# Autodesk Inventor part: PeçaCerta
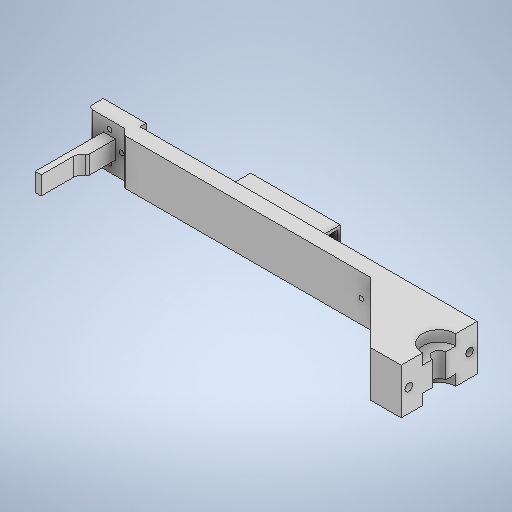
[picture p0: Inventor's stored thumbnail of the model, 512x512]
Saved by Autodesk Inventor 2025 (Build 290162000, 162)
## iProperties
Created: 2025-03
Part Number: PeçaCerta
Material: Genérico
Document SubType Name: Modeling
Designer: Ian
Density: 1 g/cm^3
Appearance: Padrão
Mass: 116.041 g
Surface Area: 272.444 cm^2
Volume: 116.041 cm^3
Author: Ian
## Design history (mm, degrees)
sketch "Esboço1"
  geometry: L1 (0, 9.81)-(0, -11.11) reference; L2 (-6.302, 0)-(16.322, 0) reference; L3 (-14.1, 15)-(235.9, 15); L4 (235.9, 15)-(235.9, -15); L5 (235.9, -15)-(-14.1, -15); L6 (-14.1, -15)-(-14.1, 15); C1 r 1.6 at (-0.001, -9.5); C2 r 1.6 at (8, 0); C3 r 1.6 at (-8, 0); C4 r 3 at (0, 0); C5 r 1.6 at (0, 9.5); 2 further points
  constraints: 12 end point, 5 centre point, 3 horizontal, 2 equal radius, 2 point on line, 2 vertical, 1 coincident, 1 midpoint, 1 parallel, 1 perpendicular
  dimensions: "d13" = 18.99994 distance of C5.centre C1.centre; "d37" = 9.21961 dimension on C1 C3; "d38" = 9.21974 dimension on C5 C3; "d39" = 9.21977 dimension on C2 C5; "d42" = 6.00008 diameter of C4; "d43" = 16 distance of C2.centre C3.centre; "d45" = 9.22072 dimension on C1 C2; "d46" = 4.5 distance edge to line of C3 L6; "d47" = 250 distance of L3.start L3.end; "d48" = 30 distance of L5.end L3.start; "d49" = 0 vertical distance of C4.centre point (-14.1, 0)
extrude "Extrusão7" new body sketch "Esboço1" distance "d50" = 10; taper "d51" = 0 deg
sketch "Esboço10"
  geometry: L1 (-135.9, 15)-(-76.9, 15) reference; L2 (-76.9, 15)-(-76.9, -15); L3 (-76.9, -15)-(-135.9, -15); L4 (-135.9, -15)-(-135.9, 15); L5 (-135.9, 15)-(-76.9, -15); L6 (-76.9, 15)-(-135.9, -15); L7 (-135.9, 13.5)-(-76.9, 13.5); L8 (-76.9, -13.5)-(-135.9, -13.5); L9 (-235.9, -15)-(-235.9, 15) reference; C1 r 1.6 at (-8, 0) reference; 2 further points
  constraints: 16 end point, 4 point on line, 3 horizontal, 3 parallel, 2 midpoint, 1 perpendicular
  dimensions: "d135" = 59 distance of L2.end L3.end; "d136" = 30 distance of L1.end L2.end; "d180" = 1.5 distance between parallel lines of L3 L8; "d181" = 1.5 distance between parallel lines of L1 L7; "d182" = 100 distance between parallel lines of L9 L4
extrude "Extrusão8" join sketch "Esboço10" distance "d58" = 10; taper "d59" = 0 deg
sketch "Esboço13"
  geometry: L1 (14.1, -15)-(-235.9, -15) reference; L2 (14.1, 15)-(14.1, -15) reference; L3 (-14.1, 15)-(14.1, 15); L4 (14.1, 15)-(14.1, -15); L5 (14.1, -15)-(-14.1, -15); L6 (-14.1, -15)-(-14.1, 15); L7 (-14.1, 15)-(14.1, -15); L8 (14.1, 15)-(-14.1, -15); C1 r 1.6 at (8, 0) reference; C2 r 3 at (0, 0) reference; C3 r 1.6 at (0.001, -9.5) reference; C4 r 1.6 at (-8, 0) reference; C5 r 1.6 at (0, 9.5) reference; C6 r 3 at (0, 0); C7 r 1.6 at (-8, 0); C8 r 1.6 at (0.001, -9.5); C9 r 1.6 at (8, 0); C10 r 1.6 at (0, 9.5); 4 further points
  constraints: 12 end point, 5 centre point, 5 coincident, 5 concentric, 2 midpoint, 2 parallel, 1 horizontal, 1 perpendicular, 1 point on line
extrude "Extrusão11" join sketch "Esboço13" distance "d70" = 4; taper "d71" = 0 deg
sketch "Esboço14"
  geometry: L1 (235.9, 15)-(-14.1, 15) reference; L2 (14.1, -15)-(-14.1, -15); L3 (-14.1, -15)-(-14.1, 15); L4 (-14.1, 15)-(14.1, 15); L5 (14.1, 15)-(14.1, -15); L6 (14.1, -15)-(-14.1, 15); L7 (-14.1, -15)-(14.1, 15); 2 further points
  constraints: 12 end point, 2 midpoint, 2 parallel, 1 horizontal, 1 perpendicular
extrude "Extrusão12" cut sketch "Esboço14" distance "d72" = 4; taper "d73" = 0 deg
sketch "Esboço15"
  geometry: L1 (0, 0)-(-221.801, 0) reference; L2 (-221.801, 0)-(-225.801, 4); L3 (-221.801, 0)-(-216.144, 0); L4 (-225.801, 4)-(-221.801, 4); L5 (-221.801, 4)-(-221.801, 0); 1 further point
  constraints: 8 end point, 2 horizontal, 1 equal length, 1 perpendicular
  dimensions: "d74" = 135 deg angle of L3 L2
extrude "Extrusão13" join sketch "Esboço15" stored distance "d75" = 4; taper "d76" = 0 deg
fillet "Arredondamento4" dims "d78" = 1
fillet "Arredondamento5" dims "d79" = 3
sketch "Esboço18"
  geometry: L1 (14.1, -15)-(235.9, -15) reference; L2 (235.9, 15)-(14.1, 15) reference; L3 (235.9, -15)-(175.9, -15); L4 (175.9, -15)-(175.9, 15); L5 (175.9, 15)-(235.9, 15); L6 (235.9, 15)-(235.9, -15); 3 further points
  constraints: 8 end point, 2 parallel, 1 horizontal, 1 perpendicular, 1 point on line
  dimensions: "d81" = 60 distance of L4.end L5.end
extrude "Extrusão14" join sketch "Esboço18" distance "d82" = 40; taper "d83" = 0 deg
sketch "Esboço19"
  geometry: L1 (0.414, 10)-(161.801, 10) reference; L2 (161.801, 10)-(201.801, 50); L3 (221.801, 50)-(161.801, 50) reference; L4 (201.801, 50)-(161.801, 50); L5 (161.801, 10)-(161.801, 50); 2 further points
  constraints: 6 end point, 1 collinear, 1 perpendicular, 1 point on line
  dimensions: "d84" = 45 deg angle of L3 L2
extrude "Extrusão15" cut sketch "Esboço19" extent not by distance; stored distance "d85" = 0; taper "d86" = 0 deg
sketch "Esboço20"
  geometry: L1 (161.801, 10)-(221.801, 10); L2 (221.801, 0)-(221.801, 50) reference; L3 (221.801, 50)-(201.801, 50) reference; L4 (201.801, 50)-(191.801, 10); C1 r 10.975 at (221.801, 25); 3 further points
  constraints: 4 end point, 2 midpoint, 1 centre point, 1 horizontal, 1 point on line
  dimensions: "d87" = 21.95 diameter of C1
extrude "Extrusão16" cut sketch "Esboço20" distance "d88" = 7; taper "d89" = 0 deg
sketch "Esboço21"
  geometry: L1 (221.801, 35.975)-(221.801, 14.025) reference; C1 r 4.25 at (221.801, 25); A1 r 10.975 centre (221.801, 25) between (221.801, 35.975) and (221.801, 14.025) reference; 3 further points
  constraints: 1 centre point, 1 coincident
  dimensions: "d90" = 8.5 diameter of C1
extrude "Extrusão17" cut sketch "Esboço21" extent not by distance; stored distance "d91" = 0; taper "d92" = 0 deg
sketch "Esboço22"
  geometry: C1 r 10.975 at (221.801, -25); A1 r 4.25 centre (221.801, -25) between (221.801, -20.75) and (221.801, -29.25) reference; 1 further point
  constraints: 1 centre point, 1 coincident
  dimensions: "d93" = 21.95 diameter of C1; "d173" = 4.25 radius of A1 (derived)
extrude "Extrusão18" cut sketch "Esboço22" distance "d94" = 7; taper "d95" = 0 deg
sketch "Esboço23"
  geometry: L1 (-14.025, 30)-(-14.025, 23) reference; L2 (-14.025, 7)-(-14.025, 0) reference; L3 (-10, 0)-(-10, 30) reference; L4 (-10, 30)-(0, 30); L5 (0, 15)-(-50, 15); L6 (-50, 30)-(-50, 0) reference; L7 (-20.75, 23)-(-20.75, 7) reference; L8 (-29.25, 7)-(-29.25, 23) reference; C1 r 2.5 at (-5, 15); C2 r 2.5 at (-45, 15)
  constraints: 4 end point, 2 centre point, 1 horizontal, 1 midpoint, 1 point on line
  dimensions: "d96" = 5 diameter of C1; "d174" = 15.75 distance from line of L7 C1.centre; "d175" = 5 diameter of C2; "d177" = 15.75 distance from line of L8 C2.centre
extrude "Extrusão19" cut sketch "Esboço23" distance "d97" = 50; taper "d98" = 0 deg
sketch "Esboço24"
  geometry: L1 (-235.9, -2.5)-(-235.9, 2.5) reference; L2 (-175.9, -15)-(-175.9, 15) reference; L3 (-183.4, -12.5)-(-208.4, -12.5); L4 (-208.4, -12.5)-(-208.4, 12.5); L5 (-208.4, 12.5)-(-183.4, 12.5); L6 (-183.4, 12.5)-(-183.4, -12.5); L7 (-183.4, -12.5)-(-208.4, 12.5); L8 (-208.4, -12.5)-(-183.4, 12.5); 1 further point
  constraints: 12 end point, 2 parallel, 1 horizontal, 1 perpendicular
  dimensions: "d101" = 25 distance of L4.end L5.end; "d102" = 25 distance of L3.end L4.end
extrude "Extrusão20" cut sketch "Esboço24" extent not by distance; stored distance "d103" = 0; taper "d104" = 0 deg
sketch "Esboço33"
  geometry: L1 (-235.9, -15)-(-235.9, 15) reference; C1 r 1.5 at (-169.604, 0); 2 further points
  constraints: 1 centre point, 1 coincident
  dimensions: "d121" = 3 diameter of C1; "d122" = 66.2965 distance from line of C1.centre L1
extrude "Extrusão25" cut sketch "Esboço33" distance "d132" = 10; taper "d133" = 0 deg
sketch "Esboço35"
  geometry: L1 (10, 30)-(10, 0) reference; L2 (8, 28)-(0, 28); L3 (0, 28)-(0, 2); L4 (0, 2)-(8, 2); L5 (8, 2)-(8, 28); L6 (0, 30)-(10, 30) reference; L7 (0, 30)-(0, 0); L8 (-0.005, 28.797)-(-0.005, 0.797); 2 further points
  constraints: 12 end point, 2 parallel, 1 horizontal, 1 perpendicular, 1 vertical
  dimensions: "d139" = 8 distance of L4.end L3.end; "d140" = 26 distance of L3.end L2.end; "d141" = 0 distance between parallel lines of L7 L3; "d142" = 2 distance between parallel lines of L6 L2
extrude "Extrusão26" cut sketch "Esboço35" stored distance "d145" = 9; taper "d146" = 0 deg
sketch "Esboço38" dims "d76" = 0
  geometry: L1 (-4, -6)-(4, -6); L2 (4, -6)-(4, 6); L3 (4, 6)-(-4, 6); L4 (-4, 6)-(-4, -6); L5 (-4, -6)-(4, 6); L6 (4, -6)-(-4, 6); 1 further point
  constraints: 12 end point, 2 midpoint, 2 parallel, 1 horizontal, 1 perpendicular
  dimensions: "d154" = 8 distance of L3.end L2.end; "d155" = 12 distance of L2.end L1.end
extrude "Extrusão29" join sketch "Esboço38" distance "d156" = 45; taper "d157" = 0 deg
sketch "Esboço39"
  geometry: L1 (8, -45)-(4, -45); L2 (4, -45)-(4, -23.875); L3 (4, -23.875)-(8, -23.875); L4 (8, -23.875)-(8, -45); L5 (8, 0)-(8, -45) reference; L6 (8, -18.318)-(8, -23.875); A1 r 5.86 centre (9.86, -23.875) between (8, -18.318) and (4, -23.875); 1 further point
  constraints: 10 end point, 2 parallel, 2 point on circle, 1 centre point, 1 collinear, 1 horizontal, 1 perpendicular, 1 point on line, 1 tangent
  dimensions: "d158" = 4 distance of L2.end L3.end; "d159" = 21.125 distance of L1.end L2.end
extrude "Extrusão30" cut sketch "Esboço39" extent not by distance; stored distance "d160" = 0; taper "d161" = 0 deg
fillet "Arredondamento6" dims "d172" = 2
sketch "Esboço42"
  geometry: L1 (208.4, 12.5)-(208.4, 0) reference; L2 (208.4, 0)-(208.4, -12.5) reference; L3 (215.9, 15)-(215.9, -15) reference; L4 (208.4, 12.5)-(215.9, 12.5); L5 (215.9, 12.5)-(215.9, -12.5); L6 (215.9, -12.5)-(208.4, -12.5); L7 (208.4, -12.5)-(208.4, 12.5); 3 further points
  constraints: 8 end point, 2 parallel, 1 horizontal, 1 perpendicular, 1 point on line
extrude "Extrusão33" cut sketch "Esboço42" distance "d178" = 10; taper "d179" = 0 deg
sketch "Esboço43"
  geometry: L1 (-76.9, -15)-(-76.9, 15) reference; L2 (-135.9, -15)-(-76.9, -15) reference; L3 (-135.9, 15)-(-135.9, -15) reference; L4 (-76.9, 15)-(-135.9, 15) reference; L5 (-135.9, 13)-(-76.9, 13) reference; L6 (-135.9, -13)-(-76.9, -13) reference; L7 (-76.9, 13)-(-135.9, 13); L8 (-135.9, 13)-(-135.9, -13); L9 (-135.9, -13)-(-76.9, -13); L10 (-76.9, -13)-(-76.9, 13); L11 (-81.9, 13)-(-81.9, -13); L12 (-130.9, 13)-(-130.9, -13); 5 further points
  constraints: 12 end point, 4 point on line, 3 perpendicular, 2 parallel, 1 horizontal
  dimensions: "d233" = 5 distance between parallel lines of L1 L11; "d234" = 5 distance between parallel lines of L3 L12
extrude "Extrusão34" cut sketch "Esboço43" stored distance "d198" = 5; taper "d199" = 0 deg
chamfer "Chanfro1" distance "d235" = 7.5; stored, may be unused: second distance "d236" = 2, angle "d237" = 45 deg
node "Sólido2"
node "Contorno projetado2"
